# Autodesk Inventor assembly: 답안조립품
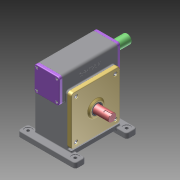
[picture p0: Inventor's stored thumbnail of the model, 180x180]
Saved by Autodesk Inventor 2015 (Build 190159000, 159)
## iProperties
Created: 2025-06
Part Number: 답안조립품
Document SubType Name: Assembly
Designer: User
Author: User
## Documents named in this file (13)
- C:\Users\User\Desktop\750603V1013\답안조립품.iam
- C:\Users\User\Desktop\750603V1013\가져온 구성요소\6각 구멍붙이 볼트 M8x20\6각 구멍붙이 볼트 M8x20.ipt
- C:\Users\User\Desktop\750603V1013\가져온 구성요소\깊은 홈 볼 베어링 6206\깊은 홈 볼 베어링 6206.ipt
- C:\Users\User\Desktop\750603V1013\가져온 구성요소\깊은 홈 볼 베어링 6209\깊은 홈 볼 베어링 6209.ipt
- C:\Users\User\Desktop\750603V1013\가져온 구성요소\뒷커버\뒷커버.ipt
- C:\Users\User\Desktop\750603V1013\본체.ipt
- C:\Users\User\Desktop\750603V1013\가져온 구성요소\앞커버\앞커버.ipt
- C:\Users\User\Desktop\750603V1013\가져온 구성요소\오일 실 30 42 7\오일 실 30 42 7.ipt
- C:\Users\User\Desktop\750603V1013\가져온 구성요소\오일 실 35 55 11\오일 실 35 55 11.ipt
- C:\Users\User\Desktop\750603V1013\가져온 구성요소\웜 샤프트\웜 샤프트.ipt
- C:\Users\User\Desktop\750603V1013\가져온 구성요소\웜 휠 커버\웜 휠 커버.ipt
- C:\Users\User\Desktop\750603V1013\가져온 구성요소\웜 휠\웜 휠.ipt
- C:\Users\User\Desktop\750603V1013\가져온 구성요소\6각 구멍붙이 볼트 M6x12\6각 구멍붙이 볼트 M6x12.ipt
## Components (12 placed, 2 different names)
1. 6각 구멍붙이 볼트 M8x20:1
2. 6각 구멍붙이 볼트 M8x20:2
3. 6각 구멍붙이 볼트 M8x20:3
4. 6각 구멍붙이 볼트 M8x20:4
5. 6각 구멍붙이 볼트 M6x12:3
6. 6각 구멍붙이 볼트 M6x12:4
7. 6각 구멍붙이 볼트 M6x12:5
8. 6각 구멍붙이 볼트 M6x12:6
9. 6각 구멍붙이 볼트 M6x12:2
10. 6각 구멍붙이 볼트 M6x12:7
11. 6각 구멍붙이 볼트 M6x12:8
12. 6각 구멍붙이 볼트 M6x12:9
